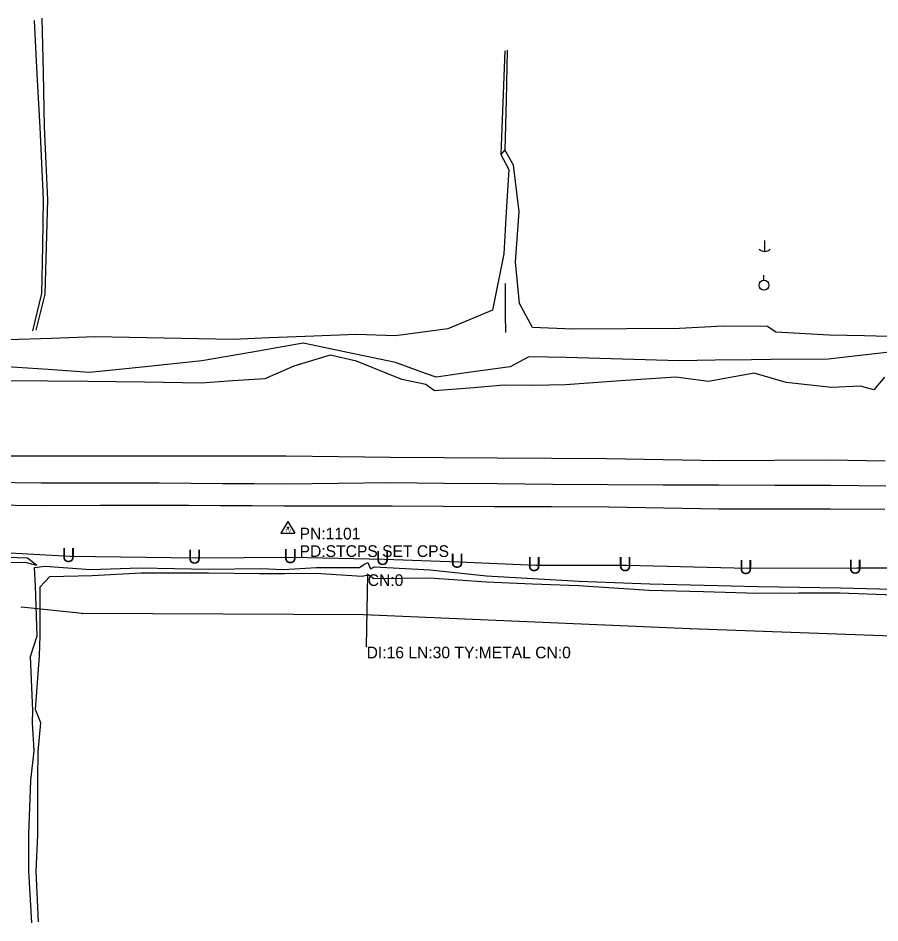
# Model space of a CAD drawing. Extents: x 1939239 to 1943096, y 531224 to 537447.
# Drawn here: x 1940300.4 to 1940668.9, y 534578.7 to 534965.8 of the extents above; entities that cross this region are included whole.
import ezdxf

# ---------------------------------------------------------------- set-up
doc = ezdxf.new("R2010")
doc.units = 0
for name, color, linetype in [('Default', 7, 'Continuous'), ('S_CROSS_DRAIN', 7, 'Continuous'), ('S_CROSS_DRAIN_ANNOT', 7, 'Continuous'), ('S_DITCHLINE', 7, 'Continuous'), ('S_DRG_PT_SYM', 7, 'Continuous'), ('S_EDGE_PAVEMENT', 7, 'Continuous'), ('S_PAVEMENT_CROWN', 7, 'Continuous'), ('S_SECONDARY_CTL', 7, 'Continuous'), ('S_SECONDARY_CTL_ANNOT', 7, 'Continuous'), ('S_UNDERGROUND_CABLE', 7, 'Continuous'), ('S_UTILITY_POLE', 7, 'Continuous'), ('S_UTL_PT_SYM', 7, 'Continuous'), ('S_WATER_UTILITIES', 7, 'Continuous')]:
    doc.layers.add(name, color=color, linetype=linetype)

msp = doc.modelspace()

# ---------------------------------------------------------------- linework, layer by layer
at = {"layer": 'S_CROSS_DRAIN'}
msp.add_line((1940449.38, 534696.91), (1940449.85, 534727.86), dxfattribs=at)
at = {"layer": 'S_DITCHLINE'}
for points in [[(1940310.53, 534965.83), (1940311.03, 534942.58), (1940311.53, 534919.34), (1940312.26, 534903.69), (1940312.98, 534888.04), (1940312.37, 534867.9), (1940311.75, 534847.76), (1940307.93, 534832.33)], [(1940307.2, 534964.76), (1940308.42, 534941.87), (1940309.65, 534918.98), (1940310.36, 534903.7), (1940311.08, 534888.42), (1940310.73, 534868.23), (1940310.39, 534848.04), (1940306.53, 534832.01)], [(1940508.45, 534951.85), (1940507.65, 534929.66), (1940506.84, 534907.46)], [(1940509.53, 534952.05), (1940509, 534930.74), (1940508.46, 534909.43)], [(1940677.37, 534829.44), (1940662.29, 534829.82), (1940647.21, 534830.19), (1940624.37, 534831.41), (1940620.81, 534833.85), (1940601.84, 534834.06), (1940583.18, 534833.09), (1940560.38, 534832.95), (1940537.57, 534832.81), (1940520.32, 534833.47), (1940514.69, 534843.71), (1940512.98, 534861.58), (1940514.56, 534883.15), (1940512.24, 534902.86), (1940508.46, 534909.43), (1940506.84, 534907.46), (1940510.22, 534901.04), (1940509.12, 534882.98), (1940508.03, 534864.92), (1940503.16, 534840.91), (1940484.14, 534832.85), (1940461.74, 534829.86), (1940445.04, 534830.45), (1940423.06, 534829.67), (1940407.67, 534829.01), (1940392.29, 534828.36), (1940377.54, 534828.63), (1940362.78, 534828.9), (1940348.03, 534829.18), (1940333.28, 534829.45), (1940314.63, 534828.78), (1940295.99, 534828.12)], [(1940508.92, 534831.31), (1940508.72, 534838.98), (1940508.76, 534852.33)], [(1940676.71, 534823.27), (1940661.7, 534821.6), (1940646.7, 534819.93), (1940622.39, 534819.82), (1940613.92, 534819.68), (1940598.45, 534819.44), (1940582.97, 534819.21), (1940558.81, 534819.9), (1940534.66, 534820.6), (1940518.76, 534820.9), (1940510.69, 534816.63), (1940494.88, 534814.43), (1940479.07, 534812.23), (1940474.58, 534813.82), (1940461.68, 534818.42), (1940441.96, 534822.57), (1940422.25, 534826.72), (1940400.57, 534822.94), (1940378.89, 534819.15), (1940354.85, 534816.69), (1940330.81, 534814.22), (1940313.14, 534815.42), (1940295.47, 534816.61)], [(1940670.81, 534812.16), (1940666.3, 534806.81), (1940660.52, 534808.36), (1940648.16, 534807.78), (1940628.72, 534809.91), (1940615.1, 534813.88), (1940595.56, 534810.31), (1940581.66, 534812.2), (1940558.05, 534810.57), (1940534.43, 534808.94), (1940520.16, 534808.58), (1940508.26, 534808.75), (1940493.32, 534807.53), (1940478.38, 534806.31), (1940474.63, 534809.12), (1940464.43, 534811.22), (1940445.09, 534818.99), (1940433.86, 534821.64), (1940418.19, 534816.89), (1940405.89, 534811.52), (1940392.24, 534810.61), (1940378.58, 534809.7), (1940354.35, 534810), (1940330.11, 534810.3), (1940313, 534810.48), (1940295.89, 534810.66)], [(1940308.34, 534731.59), (1940304.08, 534732.82), (1940282.63, 534732.99), (1940261.17, 534733.15), (1940248.33, 534733.16), (1940235.49, 534733.17), (1940222.65, 534733.19), (1940209.81, 534733.2), (1940186.73, 534734.07), (1940163.66, 534734.95), (1940149.8, 534736.27), (1940135.95, 534737.58), (1940112.32, 534737.41), (1940088.69, 534737.23), (1940074.89, 534738.4), (1940073.52, 534739.02)], [(1940304.36, 534734.79), (1940282.27, 534735.47), (1940260.17, 534736.16), (1940247.62, 534735.94), (1940235.08, 534735.72), (1940222.53, 534735.49), (1940209.99, 534735.27), (1940187.46, 534736.4), (1940164.92, 534737.53), (1940150.55, 534738.51), (1940136.18, 534739.48), (1940112.36, 534739.62), (1940088.54, 534739.76), (1940074.63, 534740.62)], [(1940308.34, 534731.59), (1940304.36, 534734.79)], [(1940306.23, 534578.72), (1940304.94, 534600.87), (1940304.99, 534616.7), (1940305.79, 534639.6), (1940307.26, 534652.37), (1940306.55, 534664.25), (1940306.66, 534669.55), (1940305.69, 534692.63), (1940308.5, 534701.53), (1940307.86, 534722.74), (1940307.3, 534730.79), (1940311.93, 534731.31), (1940331.26, 534729.89), (1940352.57, 534730.57), (1940367.17, 534730.31), (1940381.78, 534730.04), (1940404.08, 534730.29), (1940413.88, 534729.91), (1940427.99, 534730.76), (1940446.28, 534730.81), (1940448.12, 534732.09), (1940449.94, 534732.9), (1940451.04, 534730.21), (1940452.75, 534731.08), (1940476.59, 534729.84), (1940500.68, 534727.14), (1940520.5, 534726), (1940540.32, 534724.87), (1940555.38, 534724.33), (1940570.43, 534723.79), (1940593.65, 534723.21), (1940616.87, 534722.63), (1940634.43, 534722.33), (1940651.98, 534722.03), (1940674.22, 534721.5)], [(1940309.05, 534579.11), (1940308.1, 534600.83), (1940308.78, 534616.25), (1940308.76, 534640.03), (1940309, 534652.05), (1940310.07, 534664.29), (1940307.76, 534670.08), (1940309.45, 534692.91), (1940309.77, 534701.67), (1940309.85, 534722.47), (1940313.93, 534726.87), (1940331.95, 534727.42), (1940353.03, 534728.54), (1940367.43, 534728.52), (1940381.83, 534728.49), (1940403.54, 534728.19), (1940414.47, 534728.22), (1940427.56, 534728.3), (1940447.54, 534727.12), (1940449.36, 534727.55), (1940450.65, 534727.55), (1940452.49, 534726.12), (1940476.34, 534726.35), (1940500.59, 534724.59), (1940520.3, 534723.84), (1940540.02, 534723.1), (1940555.14, 534722.08), (1940570.26, 534721.07), (1940593.41, 534720.46), (1940616.55, 534719.85), (1940634.1, 534719.89), (1940651.66, 534719.94), (1940675, 534719.13)]]:
    msp.add_lwpolyline(points, dxfattribs=at)
at = {"layer": 'S_DRG_PT_SYM'}
for points in [[(1940449.85, 534727.86), (1940449.85, 534727.91), (1940449.85, 534727.86), (1940449.8, 534727.86), (1940449.85, 534727.86), (1940449.85, 534727.81), (1940449.85, 534727.86), (1940449.9, 534727.86)], [(1940449.38, 534696.91), (1940449.38, 534696.96), (1940449.38, 534696.91), (1940449.33, 534696.91), (1940449.38, 534696.91), (1940449.38, 534696.86), (1940449.38, 534696.91), (1940449.43, 534696.91)]]:
    msp.add_lwpolyline(points, dxfattribs=at)
at = {"layer": 'S_EDGE_PAVEMENT'}
for points in [[(1940288.18, 534778.5), (1940311.06, 534778.51), (1940335.89, 534778.51), (1940360.72, 534778.52), (1940374.29, 534778.51), (1940387.87, 534778.5), (1940401.44, 534778.49), (1940415.02, 534778.48), (1940437.29, 534778.22), (1940459.56, 534777.96), (1940482.36, 534777.81), (1940505.16, 534777.66), (1940528.59, 534777.56), (1940552.01, 534777.45), (1940576.23, 534777.03), (1940600.45, 534776.62), (1940623.8, 534776.73), (1940647.14, 534776.84), (1940671.09, 534776.39)], [(1940287.59, 534757.58), (1940310.67, 534757.37), (1940335.27, 534757.43), (1940359.88, 534757.48), (1940373.41, 534757.41), (1940386.94, 534757.34), (1940400.47, 534757.27), (1940414, 534757.2), (1940437.15, 534757.2), (1940460.31, 534757.21), (1940482.12, 534757.05), (1940503.94, 534756.9), (1940528.43, 534756.8), (1940552.92, 534756.71), (1940576.43, 534756.26), (1940599.94, 534755.81), (1940623.75, 534755.86), (1940647.55, 534755.91), (1940671.01, 534755.72)]]:
    msp.add_lwpolyline(points, dxfattribs=at)
at = {"layer": 'S_PAVEMENT_CROWN'}
msp.add_lwpolyline([(1940287.69, 534767.29), (1940310.25, 534766.96), (1940322.84, 534766.95), (1940335.43, 534766.95), (1940348.03, 534766.94), (1940360.62, 534766.93), (1940374.17, 534766.86), (1940387.72, 534766.78), (1940401.26, 534766.7), (1940414.81, 534766.63), (1940437.22, 534766.88), (1940459.62, 534767.12), (1940482.38, 534766.9), (1940505.14, 534766.68), (1940528.85, 534766.48), (1940552.57, 534766.29), (1940576.25, 534766.19), (1940599.94, 534766.1), (1940623.91, 534766.04), (1940647.87, 534765.97), (1940671.43, 534765.66)], dxfattribs=at)
at = {"layer": 'S_SECONDARY_CTL'}
for p, q in [((1940415.71, 534750.39), (1940412.7, 534745.43)), ((1940415.71, 534750.39), (1940418.66, 534745.43)), ((1940412.7, 534745.43), (1940418.66, 534745.43))]:
    msp.add_line(p, q, dxfattribs=at)
for radius in [0.311, 0.183, 0.103]:
    msp.add_circle((1940415.71, 534747.78), radius, dxfattribs=at)
at = {"layer": 'S_UNDERGROUND_CABLE'}
for p, q in [((1940284.37, 534737.7), (1940322.64, 534735.65)), ((1940322.64, 534735.65), (1940376.55, 534734.97)), ((1940376.55, 534734.97), (1940417.5, 534735.18)), ((1940417.5, 534735.18), (1940456.97, 534734.39)), ((1940456.97, 534734.39), (1940488.82, 534733.22)), ((1940488.82, 534733.22), (1940521.76, 534731.74)), ((1940521.76, 534731.74), (1940560.65, 534731.75)), ((1940560.65, 534731.75), (1940612.29, 534730.5)), ((1940612.29, 534730.5), (1940659.05, 534730.68)), ((1940659.05, 534730.68), (1940695.34, 534730.46))]:
    msp.add_line(p, q, dxfattribs=at)
at = {"layer": 'S_UTILITY_POLE'}
for p, q in [((1940619.57, 534870.71), (1940619.57, 534865.99)), ((1940619.17, 534853.7), (1940619.17, 534855.81))]:
    msp.add_line(p, q, dxfattribs=at)
msp.add_circle((1940619.3, 534851.56), 2.13, dxfattribs=at)
msp.add_arc((1940619.64, 534869.41), 3.41, 226.3972, 313.6028, dxfattribs=at)
at = {"layer": 'S_UTL_PT_SYM'}
for points in [[(1940301.84, 534713.87), (1940301.84, 534713.92), (1940301.84, 534713.87), (1940301.79, 534713.87), (1940301.84, 534713.87), (1940301.84, 534713.82), (1940301.84, 534713.87), (1940301.89, 534713.87)], [(1940327.8, 534711.03), (1940327.8, 534711.08), (1940327.8, 534711.03), (1940327.75, 534711.03), (1940327.8, 534711.03), (1940327.8, 534710.98), (1940327.8, 534711.03), (1940327.85, 534711.03)], [(1940448.18, 534710.58), (1940448.18, 534710.63), (1940448.18, 534710.58), (1940448.13, 534710.58), (1940448.18, 534710.58), (1940448.18, 534710.53), (1940448.18, 534710.58), (1940448.23, 534710.58)], [(1940587.78, 534704.58), (1940587.78, 534704.63), (1940587.78, 534704.58), (1940587.73, 534704.58), (1940587.78, 534704.58), (1940587.78, 534704.53), (1940587.78, 534704.58), (1940587.83, 534704.58)]]:
    msp.add_lwpolyline(points, dxfattribs=at)
at = {"layer": 'S_WATER_UTILITIES'}
for p, q in [((1940327.8, 534711.03), (1940301.84, 534713.87)), ((1940448.18, 534710.58), (1940327.8, 534711.03)), ((1940587.78, 534704.58), (1940448.18, 534710.58)), ((1940690.26, 534700.72), (1940587.78, 534704.58))]:
    msp.add_line(p, q, dxfattribs=at)

# ---------------------------------------------------------------- texts
at = {"layer": 'Default'}
for p in [(1940319.01, 534733.1), (1940372.92, 534732.43), (1940413.87, 534732.64), (1940453.34, 534731.85), (1940485.19, 534730.67), (1940518.14, 534729.2), (1940557.02, 534729.21), (1940608.66, 534727.96), (1940655.42, 534728.14)]:
    msp.add_text('U', height=6, dxfattribs=at).set_placement(p)
at = {"layer": 'S_CROSS_DRAIN_ANNOT'}
for s, p in [('CN:0', (1940449.85, 534722.86)), ('DI:16 LN:30 TY:METAL CN:0', (1940449.38, 534691.91))]:
    msp.add_text(s, height=5, dxfattribs=at).set_placement(p)
at = {"layer": 'S_SECONDARY_CTL'}
msp.add_text('TV', height=1.5, dxfattribs=at).set_placement((1940414.51, 534745.77))
at = {"layer": 'S_SECONDARY_CTL_ANNOT'}
for s, p in [('PN:1101', (1940420.71, 534742.78)), ('PD:STCPS SET CPS', (1940420.71, 534735.28))]:
    msp.add_text(s, height=5, dxfattribs=at).set_placement(p)

doc.saveas('drawing.dxf')
